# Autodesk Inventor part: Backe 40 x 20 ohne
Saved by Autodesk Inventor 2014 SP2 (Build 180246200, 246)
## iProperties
Created: 2015-06
Part Number: Backe 40 x 20 ohne
Material: Generisch
Document SubType Name: Modeling
Designer: e_krauts
Density: 1 g/cm^3
Appearance: Vorgabe
Sending System: SolidWorks 2011
Last Author: e_boekem
Author: e_krauts
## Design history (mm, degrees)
node "Backe 40 x 20 ohne.ipt1"
node "Fase11"
node "Aufsatz-Linear austragen5"
node "Basis1"
node "Basis2"
